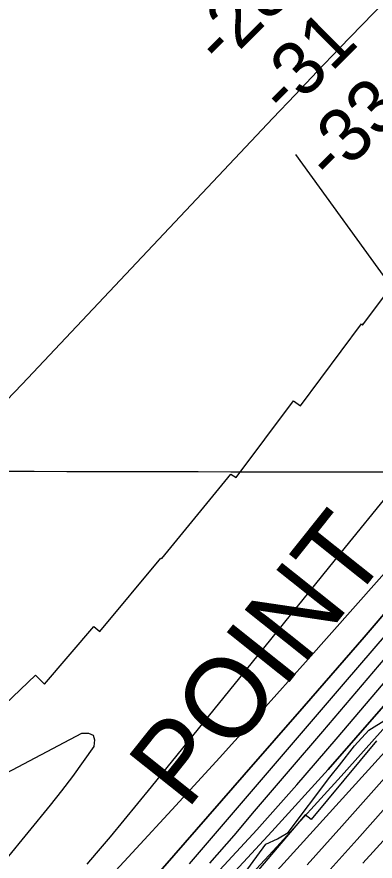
# Model space of a CAD drawing. Extents: x 3208593 to 3246461, y 812903 to 838290.
# Drawn here: x 3214527 to 3214974, y 829962 to 831014 of the extents above; entities that cross this region are included whole.
import ezdxf

# ---------------------------------------------------------------- set-up
doc = ezdxf.new("R2010")
doc.units = 0
for name, color, linetype in [('V-GRID-MAJR', 7, 'Continuous'), ('V-RIVR-EDGE', 7, 'Continuous'), ('V-RIVR-RANG', 7, 'Continuous'), ('V-RRAP-RVMT', 7, 'Continuous'), ('V-RRAP-RVMT-IDEN', 7, 'Continuous'), ('V-TOPO-DPTH', 7, 'Continuous'), ('V-TOPO-MAJR', 7, 'Continuous'), ('V-TOPO-MINR', 7, 'Continuous'), ('V-TOPO-WATR', 7, 'Continuous')]:
    doc.layers.add(name, color=color, linetype=linetype)

msp = doc.modelspace()

# ---------------------------------------------------------------- linework, layer by layer
at = {"layer": 'V-GRID-MAJR'}
msp.add_spline([(3212790.146, 830450.674), (3218024.231, 830441.158), (3223258.319, 830432.403), (3228492.407, 830424.409), (3233726.4960000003, 830417.177), (3238960.5870000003, 830410.706), (3244194.678, 830404.996), (3244194.679, 830404.996)], degree=3, dxfattribs=at)
at = {"layer": 'V-RIVR-EDGE'}
msp.add_lwpolyline([(3214810.3139080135, 829945.9178971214), (3214837.3552132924, 829982.7987625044), (3214852.1503376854, 829989.2823661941), (3214865.2099804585, 829997.0742987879), (3214917.1073852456, 830066.0599619), (3214929.315947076, 830081.2435451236), (3214948.066153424, 830105.1045364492), (3214965.936258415, 830124.620912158), (3214987.704479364, 830138.4768195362)], dxfattribs=at)
at = {"layer": 'V-RIVR-RANG'}
msp.add_line((3215578.4224, 829870.1206999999), (3214874.8604, 830842.2320999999), dxfattribs=at)
at = {"layer": 'V-RRAP-RVMT'}
for p, q in [((3214958.085000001, 830629.7209999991), (3215037.096000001, 830735.1249999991)), ((3214880.562000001, 830528.885999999), (3214956.472000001, 830631.1419999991)), ((3214956.472000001, 830631.1419999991), (3214958.085000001, 830629.7209999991)), ((3214800.263000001, 830439.682999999), (3214871.8880000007, 830535.3309999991)), ((3214871.8880000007, 830535.3309999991), (3214880.562000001, 830528.885999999)), ((3214707.609000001, 830338.9739999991), (3214793.892000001, 830443.680999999)), ((3214793.892000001, 830443.680999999), (3214800.263000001, 830439.682999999)), ((3214630.439000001, 830247.6209999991), (3214706.542000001, 830339.393999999)), ((3214706.542000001, 830339.393999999), (3214707.609000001, 830338.9739999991)), ((3214561.464000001, 830181.9789999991), (3214622.873000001, 830254.155999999)), ((3214622.873000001, 830254.155999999), (3214630.439000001, 830247.6209999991)), ((3214449.039000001, 830096.7019999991), (3214550.265000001, 830193.4899999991)), ((3214550.265000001, 830193.4899999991), (3214561.464000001, 830181.9789999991)), ((3214975.544000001, 830111.6669999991), (3214893.987000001, 830013.545999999)), ((3214886.417000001, 830019.3729999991), (3214807.8940000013, 829927.1499999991)), ((3214893.987000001, 830013.545999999), (3214886.417000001, 830019.3729999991))]:
    msp.add_line(p, q, dxfattribs=at)
at = {"layer": 'V-TOPO-DPTH'}
for points in [[(3214485.106902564, 830505.5930689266), (3214533.7312984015, 830556.063275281), (3214846.216147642, 830887.5451478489), (3214873.810328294, 830916.6833190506), (3214901.4927483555, 830945.7370304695), (3214929.3075275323, 830974.6640522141), (3214957.210546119, 831003.5066141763), (3215381.863304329, 831440.457690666)], [(3214485.106902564, 830505.5930689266), (3214533.7312984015, 830556.063275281), (3214846.216147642, 830887.5451478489), (3214873.810328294, 830916.6833190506), (3214901.4927483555, 830945.7370304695), (3214929.3075275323, 830974.6640522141), (3214957.210546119, 831003.5066141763), (3215381.863304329, 831440.457690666)], [(3214673.343900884, 829753.5713146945), (3214997.624010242, 830111.010931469), (3215055.458069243, 830175.4951137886), (3215112.795318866, 830240.4130659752), (3215169.3873544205, 830305.9816729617), (3215225.4825805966, 830371.9840498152), (3215311.284137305, 830474.1156489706), (3215324.003943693, 830489.459544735), (3215336.5879083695, 830504.9125874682), (3215348.968110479, 830520.5293506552), (3215361.212470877, 830536.2552608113), (3215444.3398485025, 830644.4757969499), (3215497.869319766, 830714.5272271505), (3215551.1632633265, 830784.7564591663), (3215604.103915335, 830855.2523939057), (3215656.8090396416, 830925.9261304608), (3215956.264365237, 831329.5846153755)], [(3215811.806768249, 831323.6638253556), (3215495.9095204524, 830895.0223280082), (3215456.9770012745, 830842.7968218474), (3215417.666352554, 830790.8607988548), (3215377.788509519, 830739.3590006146), (3215337.5325369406, 830688.1466855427), (3215272.205127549, 830605.9708245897), (3215264.275071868, 830596.1082863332), (3215256.272887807, 830586.3052958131), (3215248.1625111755, 830576.5916268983), (3215239.9800061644, 830566.9375057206), (3215108.338379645, 830413.354624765), (3215034.1647350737, 830327.0542594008), (3214959.8361402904, 830240.8879221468), (3214885.275120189, 830154.9226270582), (3214810.5591498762, 830069.0913600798), (3214617.8913175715, 829848.363385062), (3214604.344339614, 829833.1674757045), (3214590.5900403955, 829818.1656801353), (3214576.524759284, 829803.455055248), (3214562.2521569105, 829788.9385441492), (3214547.5967734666, 829774.8228120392), (3214532.6393324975, 829761.0462590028), (3214517.22880524, 829747.778474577)], [(3214517.22880524, 829747.778474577), (3214532.6393324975, 829761.0462590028), (3214547.5967734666, 829774.8228120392), (3214562.2521569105, 829788.9385441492), (3214576.524759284, 829803.455055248), (3214590.5900403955, 829818.1656801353), (3214604.344339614, 829833.1674757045), (3214617.8913175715, 829848.363385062), (3214810.5591498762, 830069.0913600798), (3214885.275120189, 830154.9226270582), (3214959.8361402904, 830240.8879221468), (3215034.1647350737, 830327.0542594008), (3215108.338379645, 830413.354624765), (3215239.9800061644, 830566.9375057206), (3215248.1625111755, 830576.5916268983), (3215256.272887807, 830586.3052958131), (3215264.275071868, 830596.1082863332), (3215272.205127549, 830605.9708245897), (3215337.5325369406, 830688.1466855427), (3215377.788509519, 830739.3590006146), (3215417.666352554, 830790.8607988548), (3215456.9770012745, 830842.7968218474), (3215495.9095204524, 830895.0223280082), (3215811.806768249, 831323.6638253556)], [(3215743.6196937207, 831108.179424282), (3215311.0520736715, 830539.726813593), (3215309.133051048, 830537.2297658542), (3215307.198284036, 830534.7450990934), (3215305.239900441, 830532.2790037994), (3215303.265772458, 830529.825289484), (3215301.2718623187, 830527.3874855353), (3215299.2673247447, 830524.9585109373), (3215297.2468460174, 830522.5427803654), (3215295.215739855, 830520.1358791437), (3215293.56552134, 830518.1933418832), (3215290.7019206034, 830514.8212974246), (3215287.839101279, 830511.4485899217), (3215284.9774540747, 830508.0748878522), (3215282.116588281, 830504.7005227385), (3215052.5996275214, 830233.8919891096), (3214984.2978527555, 830154.5693947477), (3214915.1816577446, 830075.9743798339), (3214844.843832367, 829998.4707340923), (3214773.691586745, 829921.694667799)], [(3215743.6196937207, 831108.179424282), (3215311.0520736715, 830539.726813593), (3215309.133051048, 830537.2297658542), (3215307.198284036, 830534.7450990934), (3215305.239900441, 830532.2790037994), (3215303.265772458, 830529.825289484), (3215301.2718623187, 830527.3874855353), (3215299.2673247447, 830524.9585109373), (3215297.2468460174, 830522.5427803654), (3215295.215739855, 830520.1358791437), (3215293.56552134, 830518.1933418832), (3215290.7019206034, 830514.8212974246), (3215287.839101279, 830511.4485899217), (3215284.9774540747, 830508.0748878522), (3215282.116588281, 830504.7005227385), (3215052.5996275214, 830233.8919891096), (3214984.2978527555, 830154.5693947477), (3214915.1816577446, 830075.9743798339), (3214844.843832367, 829998.4707340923), (3214773.691586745, 829921.694667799)], [(3214767.768868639, 829959.2345721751), (3214797.7663244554, 829993.6949665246), (3214823.355015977, 830023.7070315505), (3214865.808702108, 830073.4828073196), (3214908.273337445, 830123.2492372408), (3214950.754396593, 830173.0016483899), (3214993.2464049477, 830222.7447136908), (3215054.7483022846, 830294.7175596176), (3215092.5379846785, 830339.1148533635), (3215130.212614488, 830383.6091835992), (3215167.714665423, 830428.2490685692), (3215205.101663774, 830472.9859900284), (3215242.3361619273, 830517.7161553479), (3215260.9027577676, 830540.2547138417), (3215279.313576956, 830562.9184948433), (3215297.4907311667, 830585.7701096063), (3215315.512108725, 830608.7469468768), (3215457.7699582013, 830792.0526017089), (3215532.8134396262, 830889.8363032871), (3215607.1454455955, 830988.1518997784), (3215680.410238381, 831087.2653386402)], [(3214767.768868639, 829959.2345721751), (3214797.7663244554, 829993.6949665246), (3214823.355015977, 830023.7070315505), (3214865.808702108, 830073.4828073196), (3214908.273337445, 830123.2492372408), (3214950.754396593, 830173.0016483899), (3214993.2464049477, 830222.7447136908), (3215054.7483022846, 830294.7175596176), (3215092.5379846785, 830339.1148533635), (3215130.212614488, 830383.6091835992), (3215167.714665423, 830428.2490685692), (3215205.101663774, 830472.9859900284), (3215242.3361619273, 830517.7161553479), (3215260.9027577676, 830540.2547138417), (3215279.313576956, 830562.9184948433), (3215297.4907311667, 830585.7701096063), (3215315.512108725, 830608.7469468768), (3215457.7699582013, 830792.0526017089), (3215532.8134396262, 830889.8363032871), (3215607.1454455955, 830988.1518997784), (3215680.410238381, 831087.2653386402)], [(3215452.1797223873, 831035.5105430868), (3215417.3149228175, 830983.1105379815), (3215381.88753418, 830931.0783894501), (3215348.480044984, 830882.8479489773), (3215321.9180322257, 830845.0001517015), (3215295.0486172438, 830807.3747489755), (3215267.7180989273, 830770.0829380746), (3215240.080178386, 830733.0135217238), (3215198.003046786, 830677.2964577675), (3215191.127888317, 830668.2877525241), (3215184.192515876, 830659.3261357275), (3215177.166822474, 830650.4351516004), (3215170.080915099, 830641.5912559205), (3215057.6927338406, 830502.7652335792), (3214994.368520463, 830424.5428777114), (3214931.0455814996, 830346.319490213), (3214867.7245541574, 830268.0945552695), (3214804.404801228, 830189.868588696), (3214694.436108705, 830054.0085796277), (3214677.479588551, 830033.2354119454), (3214660.4098356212, 830012.5565014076), (3214643.1702335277, 829992.0189765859), (3214625.8173986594, 829971.5757089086), (3214614.165986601, 829957.963355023)], [(3215452.1797223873, 831035.5105430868), (3215417.3149228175, 830983.1105379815), (3215381.88753418, 830931.0783894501), (3215348.480044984, 830882.8479489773), (3215321.9180322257, 830845.0001517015), (3215295.0486172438, 830807.3747489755), (3215267.7180989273, 830770.0829380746), (3215240.080178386, 830733.0135217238), (3215198.003046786, 830677.2964577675), (3215191.127888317, 830668.2877525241), (3215184.192515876, 830659.3261357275), (3215177.166822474, 830650.4351516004), (3215170.080915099, 830641.5912559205), (3215057.6927338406, 830502.7652335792), (3214994.368520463, 830424.5428777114), (3214931.0455814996, 830346.319490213), (3214867.7245541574, 830268.0945552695), (3214804.404801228, 830189.868588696), (3214694.436108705, 830054.0085796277), (3214677.479588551, 830033.2354119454), (3214660.4098356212, 830012.5565014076), (3214643.1702335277, 829992.0189765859), (3214625.8173986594, 829971.5757089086), (3214614.165986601, 829957.963355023)], [(3215527.663840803, 831022.434556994), (3215468.9393426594, 830938.0586085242), (3215239.697203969, 830608.9507390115), (3215238.5003393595, 830607.2501817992), (3215236.0683110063, 830603.876678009), (3215234.833147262, 830602.203731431), (3215232.285461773, 830598.9188014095), (3215230.9629011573, 830597.315610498), (3215229.6159816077, 830595.7320566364), (3215227.6511861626, 830593.4742447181), (3215225.2995024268, 830590.7801132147), (3215222.9423845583, 830588.0907591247), (3215220.5771154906, 830585.4085711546), (3215218.2064122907, 830582.7311605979), (3214886.820706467, 830209.6150814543), (3214833.306857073, 830149.7634587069), (3214779.530138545, 830090.1505561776), (3214725.3591163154, 830030.8957339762), (3214670.92522495, 829971.8796319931), (3214588.8134620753, 829883.446182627)], [(3214588.8134620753, 829883.446182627), (3214670.92522495, 829971.8796319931), (3214725.3591163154, 830030.8957339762), (3214779.530138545, 830090.1505561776), (3214833.306857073, 830149.7634587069), (3214886.820706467, 830209.6150814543), (3215218.2064122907, 830582.7311605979), (3215220.5771154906, 830585.4085711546), (3215222.9423845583, 830588.0907591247), (3215225.2995024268, 830590.7801132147), (3215227.6511861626, 830593.4742447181), (3215229.6159816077, 830595.7320566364), (3215230.9629011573, 830597.315610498), (3215232.285461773, 830598.9188014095), (3215234.833147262, 830602.203731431), (3215236.0683110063, 830603.876678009), (3215238.5003393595, 830607.2501817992), (3215239.697203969, 830608.9507390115), (3215468.9393426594, 830938.0586085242), (3215527.663840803, 831022.434556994)]]:
    msp.add_lwpolyline(points, dxfattribs=at)
at = {"layer": 'V-TOPO-MAJR'}
for points in [[(3214958.5156072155, 829959.1537098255), (3215043.3379101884, 830052.6545933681), (3215127.127113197, 830147.0823846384), (3215210.2275828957, 830242.1281143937), (3215379.9533724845, 830438.4184097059), (3215385.1327350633, 830444.4840541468), (3215390.26132691, 830450.5917959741), (3215395.313762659, 830456.7626838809), (3215400.315427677, 830462.9756691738), (3215442.165720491, 830515.626661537), (3215467.8579613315, 830548.3466512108), (3215493.288315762, 830581.2664741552), (3215518.325840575, 830614.4860470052), (3215543.1014789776, 830647.905453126), (3215609.320870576, 830738.3455113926), (3215664.4167301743, 830813.4294953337), (3215719.61652428, 830888.4368244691), (3215774.9722201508, 830963.3291713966), (3215830.4318505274, 831038.1448635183)], [(3214470.145547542, 830048.4646893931), (3214608.112130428, 830121.0068039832), (3214616.3448258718, 830120.911377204), (3214621.990911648, 830118.5025671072), (3214623.757082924, 830112.6236820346), (3214622.9366445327, 830104.4314136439), (3214609.8663802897, 830085.6872764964), (3214596.468071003, 830067.187507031), (3214582.577694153, 830049.0542890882), (3214568.35927226, 830031.165438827), (3214512.6640865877, 829962.9934878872)]]:
    msp.add_lwpolyline(points, dxfattribs=at)
at = {"layer": 'V-TOPO-MINR'}
for points in [[(3214485.106902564, 830505.5930689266), (3214533.7312984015, 830556.063275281), (3214846.216147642, 830887.5451478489), (3214873.810328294, 830916.6833190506), (3214901.4927483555, 830945.7370304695), (3214929.3075275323, 830974.6640522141), (3214957.210546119, 831003.5066141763), (3215381.863304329, 831440.457690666)], [(3214673.343900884, 829753.5713146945), (3214997.624010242, 830111.010931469), (3215055.458069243, 830175.4951137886), (3215112.795318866, 830240.4130659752), (3215169.3873544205, 830305.9816729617), (3215225.4825805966, 830371.9840498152), (3215311.284137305, 830474.1156489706), (3215324.003943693, 830489.459544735), (3215336.5879083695, 830504.9125874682), (3215348.968110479, 830520.5293506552), (3215361.212470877, 830536.2552608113), (3215444.3398485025, 830644.4757969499), (3215497.869319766, 830714.5272271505), (3215551.1632633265, 830784.7564591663), (3215604.103915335, 830855.2523939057), (3215656.8090396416, 830925.9261304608), (3215956.264365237, 831329.5846153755)], [(3214517.22880524, 829747.778474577), (3214532.6393324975, 829761.0462590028), (3214547.5967734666, 829774.8228120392), (3214562.2521569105, 829788.9385441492), (3214576.524759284, 829803.455055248), (3214590.5900403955, 829818.1656801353), (3214604.344339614, 829833.1674757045), (3214617.8913175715, 829848.363385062), (3214810.5591498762, 830069.0913600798), (3214885.275120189, 830154.9226270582), (3214959.8361402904, 830240.8879221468), (3215034.1647350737, 830327.0542594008), (3215108.338379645, 830413.354624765), (3215239.9800061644, 830566.9375057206), (3215248.1625111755, 830576.5916268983), (3215256.272887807, 830586.3052958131), (3215264.275071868, 830596.1082863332), (3215272.205127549, 830605.9708245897), (3215337.5325369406, 830688.1466855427), (3215377.788509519, 830739.3590006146), (3215417.666352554, 830790.8607988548), (3215456.9770012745, 830842.7968218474), (3215495.9095204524, 830895.0223280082), (3215811.806768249, 831323.6638253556)], [(3214767.768868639, 829959.2345721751), (3214797.7663244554, 829993.6949665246), (3214823.355015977, 830023.7070315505), (3214865.808702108, 830073.4828073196), (3214908.273337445, 830123.2492372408), (3214950.754396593, 830173.0016483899), (3214993.2464049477, 830222.7447136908), (3215054.7483022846, 830294.7175596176), (3215092.5379846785, 830339.1148533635), (3215130.212614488, 830383.6091835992), (3215167.714665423, 830428.2490685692), (3215205.101663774, 830472.9859900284), (3215242.3361619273, 830517.7161553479), (3215260.9027577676, 830540.2547138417), (3215279.313576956, 830562.9184948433), (3215297.4907311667, 830585.7701096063), (3215315.512108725, 830608.7469468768), (3215457.7699582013, 830792.0526017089), (3215532.8134396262, 830889.8363032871), (3215607.1454455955, 830988.1518997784), (3215680.410238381, 831087.2653386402)], [(3214689.3199345, 829804.3738271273), (3214850.996965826, 829979.2441390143), (3214931.5229479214, 830067.5555153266), (3215011.225116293, 830156.5941496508), (3215089.691564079, 830246.7236709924), (3215167.3341981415, 830337.5804503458), (3215309.951455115, 830506.8196963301), (3215315.6265376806, 830513.6355572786), (3215321.2472504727, 830520.4954317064), (3215326.786408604, 830527.4213263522), (3215332.271196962, 830534.391234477), (3215372.1281855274, 830585.6615817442), (3215397.420450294, 830618.3610107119), (3215422.6057511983, 830651.1422036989), (3215447.630606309, 830684.0460427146), (3215472.5484975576, 830717.0316457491), (3215689.1767696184, 831005.2592038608), (3215725.9091878, 831054.0917409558)], [(3214742.343880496, 829958.1091893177), (3214934.3874713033, 830182.217620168), (3214990.1633481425, 830247.4572718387), (3215045.839373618, 830312.7818294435), (3215101.3656220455, 830378.2337459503), (3215156.7920191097, 830443.7705683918), (3215241.0359144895, 830543.6132306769), (3215254.18101239, 830559.3611475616), (3215267.2135236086, 830575.2007010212), (3215280.0771548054, 830591.177709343), (3215292.8281993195, 830607.2463542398), (3215390.117652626, 830731.1943788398), (3215451.012757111, 830809.6208431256), (3215511.3530640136, 830888.4672822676), (3215570.861174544, 830967.943683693), (3215629.814487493, 831047.8400599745)], [(3214898.7171396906, 829930.2984672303), (3214951.104858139, 829988.4516545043), (3215003.0175797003, 830047.0380766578), (3215217.404937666, 830292.0102889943), (3215236.420828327, 830313.7154134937), (3215255.452291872, 830335.4068599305), (3215274.507114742, 830357.0777892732), (3215293.577510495, 830378.7350405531), (3215311.2299046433, 830398.7601813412), (3215321.431576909, 830410.4409304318), (3215331.560988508, 830422.1834364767), (3215341.5820091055, 830434.0185779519), (3215351.530769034, 830445.9154763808), (3215361.34224266, 830457.9244005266), (3215371.0429904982, 830470.0208854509), (3215380.5776496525, 830482.2487115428), (3215390.0015830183, 830494.5640984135), (3215715.1054808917, 830925.4818296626), (3215762.8377604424, 830989.2440336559), (3215810.2503192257, 831053.2412585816)], [(3215452.1797223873, 831035.5105430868), (3215417.3149228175, 830983.1105379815), (3215381.88753418, 830931.0783894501), (3215348.480044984, 830882.8479489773), (3215321.9180322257, 830845.0001517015), (3215295.0486172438, 830807.3747489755), (3215267.7180989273, 830770.0829380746), (3215240.080178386, 830733.0135217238), (3215198.003046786, 830677.2964577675), (3215191.127888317, 830668.2877525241), (3215184.192515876, 830659.3261357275), (3215177.166822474, 830650.4351516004), (3215170.080915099, 830641.5912559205), (3215057.6927338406, 830502.7652335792), (3214994.368520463, 830424.5428777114), (3214931.0455814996, 830346.319490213), (3214867.7245541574, 830268.0945552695), (3214804.404801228, 830189.868588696), (3214694.436108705, 830054.0085796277), (3214677.479588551, 830033.2354119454), (3214660.4098356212, 830012.5565014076), (3214643.1702335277, 829992.0189765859), (3214625.8173986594, 829971.5757089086), (3214614.165986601, 829957.963355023)], [(3214588.8134620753, 829883.446182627), (3214670.92522495, 829971.8796319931), (3214725.3591163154, 830030.8957339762), (3214779.530138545, 830090.1505561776), (3214833.306857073, 830149.7634587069), (3214886.820706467, 830209.6150814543), (3215218.2064122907, 830582.7311605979), (3215220.5771154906, 830585.4085711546), (3215222.9423845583, 830588.0907591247), (3215225.2995024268, 830590.7801132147), (3215227.6511861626, 830593.4742447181), (3215229.6159816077, 830595.7320566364), (3215230.9629011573, 830597.315610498), (3215232.285461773, 830598.9188014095), (3215234.833147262, 830602.203731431), (3215236.0683110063, 830603.876678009), (3215238.5003393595, 830607.2501817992), (3215239.697203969, 830608.9507390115), (3215468.9393426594, 830938.0586085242), (3215527.663840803, 831022.434556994)], [(3214775.270071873, 829945.4030311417), (3214826.1449427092, 830000.6750357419), (3214876.0046212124, 830056.8645315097), (3214925.1875048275, 830113.665688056), (3215043.1446467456, 830252.4283013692), (3215071.7482372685, 830286.0650267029), (3215100.359727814, 830319.695028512), (3215128.983068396, 830353.3149450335), (3215157.614309, 830386.9281380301), (3215175.0061001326, 830407.3388846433), (3215194.884645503, 830430.7941559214), (3215214.679563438, 830454.3194149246), (3215234.349040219, 830477.9496555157), (3215253.9348895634, 830501.649883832), (3215273.338900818, 830525.4972616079), (3215292.584130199, 830549.4708177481), (3215311.591186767, 830573.6336414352), (3215330.4394614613, 830597.9226434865), (3215599.514186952, 830948.2333587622), (3215652.874355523, 831018.5276343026)], [(3214888.994022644, 829956.7955092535), (3214932.2183937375, 830005.303500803), (3214975.4643417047, 830053.7922570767), (3215018.7246742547, 830102.2681898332), (3215153.489950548, 830253.2135824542), (3215187.5208210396, 830291.7151952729), (3215221.292974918, 830330.4401729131), (3215254.677053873, 830369.5001977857), (3215287.8024162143, 830408.7835874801), (3215312.8510216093, 830438.791267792), (3215333.0888035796, 830463.3732328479), (3215353.1010879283, 830488.134925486), (3215372.7751258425, 830513.1662094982), (3215392.223666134, 830538.3772210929), (3215528.5633090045, 830717.6180719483), (3215604.5570777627, 830818.1590467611), (3215680.139961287, 830919.0060202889), (3215755.106516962, 831020.311991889)]]:
    msp.add_lwpolyline(points, dxfattribs=at)
at = {"layer": 'V-TOPO-WATR'}
msp.add_lwpolyline([(3214773.691586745, 829921.694667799), (3214844.843832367, 829998.4707340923), (3214915.1816577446, 830075.9743798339), (3214984.2978527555, 830154.5693947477), (3215052.5996275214, 830233.8919891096), (3215282.116588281, 830504.7005227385), (3215284.9774540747, 830508.0748878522), (3215287.839101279, 830511.4485899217), (3215290.7019206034, 830514.8212974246), (3215293.56552134, 830518.1933418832), (3215295.215739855, 830520.1358791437), (3215297.2468460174, 830522.5427803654), (3215299.2673247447, 830524.9585109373), (3215301.2718623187, 830527.3874855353), (3215303.265772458, 830529.825289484), (3215305.239900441, 830532.2790037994), (3215307.198284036, 830534.7450990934), (3215309.133051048, 830537.2297658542), (3215311.0520736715, 830539.726813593), (3215743.6196937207, 831108.179424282)], dxfattribs=at)

# ---------------------------------------------------------------- texts
at = {"layer": 'V-RIVR-RANG'}
for s, p in [('-28', (3214782.504877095, 830949.6011437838)), ('-31', (3214862.683659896, 830888.2823558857)), ('-33', (3214920.764756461, 830805.0418127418))]:
    msp.add_text(s, height=66.99999999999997, rotation=44.77230555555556, dxfattribs=at).set_placement(p)
at = {"layer": 'V-RRAP-RVMT-IDEN'}
msp.add_text('POINT ', height=99.999801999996, rotation=51.44280068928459, dxfattribs=at).set_placement((3214738.8593793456, 830023.8923673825))

doc.saveas('drawing.dxf')
